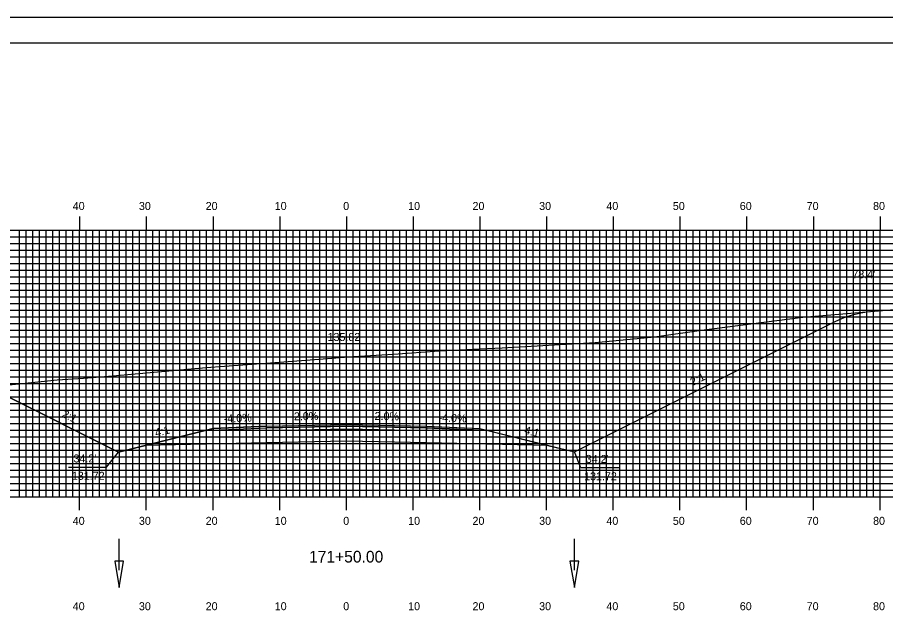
# Model space of a CAD drawing. Extents: x 1782647 to 1782990, y 442591 to 442811.
# Drawn here: x 1782763.6 to 1782893.8, y 442721.2 to 442810.5 of the extents above; entities that cross this region are included whole.
import ezdxf

# ---------------------------------------------------------------- set-up
doc = ezdxf.new("R2010")
doc.units = 0
for name, color, linetype in [('ANNOTATION', 7, 'Continuous'), ('BORDER', 7, 'Continuous'), ('D_Drainage_Ditch_Line', 7, 'Continuous'), ('D_Roadway_Centerline', 7, 'Continuous'), ('D_Roadway_Centerline_Text', 7, 'Continuous'), ('D_Roadway_Edge_Shoulder', 7, 'Continuous'), ('D_Roadway_Edge_TW', 7, 'Continuous'), ('D_Roadway_Pavement', 7, 'Continuous'), ('D_Roadway_SlopeLines', 7, 'Continuous'), ('D_Roadway_SubGrade', 7, 'Continuous'), ('D_Text_Standard', 7, 'Continuous'), ('H_V ANNOTATION', 7, 'Continuous'), ('MAJOR', 7, 'Continuous'), ('MINOR', 7, 'Continuous'), ('PLOT BOUNDARY', 7, 'Continuous'), ('S_Roadway_Centerline', 7, 'Continuous')]:
    doc.layers.add(name, color=color, linetype=linetype)

msp = doc.modelspace()

# ---------------------------------------------------------------- linework, layer by layer
at = {"layer": 'ANNOTATION'}
for points in [[(1782771.3, 442743.1), (1782776.99, 442743.1), (1782778.77, 442745.38)], [(1782853.78, 442743.03), (1782848.09, 442743.03), (1782847.12, 442745.39)]]:
    msp.add_lwpolyline(points, dxfattribs=at)
at = {"layer": 'BORDER'}
msp.add_lwpolyline([(1782663.35, 442596.67), (1782983.35, 442596.67), (1782983.35, 442806.67), (1782663.35, 442806.67)], close=True, dxfattribs=at)
at = {"layer": 'D_Drainage_Ditch_Line'}
for p, q in [((1782778.87, 442727.69), (1782778.87, 442732.39)), ((1782847.12, 442727.69), (1782847.12, 442732.39))]:
    msp.add_line(p, q, dxfattribs=at)
for points in [[(1782779.53, 442729), (1782778.21, 442729), (1782778.87, 442725.07)], [(1782847.77, 442729), (1782846.46, 442729), (1782847.12, 442725.07)]]:
    msp.add_lwpolyline(points, close=True, dxfattribs=at)
at = {"layer": 'D_Roadway_Centerline'}
msp.add_lwpolyline([(1782756.76, 442754.88), (1782758.01, 442754.92), (1782759.26, 442754.76), (1782760.51, 442754.42), (1782761.76, 442753.89), (1782778.77, 442745.38), (1782782.77, 442746.38), (1782792.95, 442748.93), (1782800.95, 442749.25), (1782812.95, 442749.49), (1782824.95, 442749.25), (1782832.95, 442748.93), (1782843.12, 442746.38), (1782847.12, 442745.39), (1782886.31, 442764.98), (1782887.56, 442765.54), (1782888.81, 442765.97), (1782890.06, 442766.27), (1782891.31, 442766.44)], dxfattribs=at)
at = {"layer": 'D_Roadway_Edge_Shoulder'}
for points in [[(1782800.95, 442749.25), (1782792.95, 442748.93), (1782792.95, 442748.68), (1782800.95, 442749)], [(1782824.95, 442749.25), (1782832.95, 442748.93), (1782832.95, 442748.68), (1782824.95, 442749)]]:
    msp.add_lwpolyline(points, close=True, dxfattribs=at)
at = {"layer": 'D_Roadway_Edge_TW'}
msp.add_lwpolyline([(1782800.95, 442749), (1782800.95, 442749.25), (1782812.95, 442749.49), (1782824.95, 442749.25), (1782824.95, 442749), (1782812.95, 442749.24)], close=True, dxfattribs=at)
at = {"layer": 'D_Roadway_Pavement'}
msp.add_lwpolyline([(1782800.95, 442748.58), (1782800.95, 442749), (1782812.95, 442749.24), (1782824.95, 442749), (1782824.95, 442748.58), (1782812.95, 442748.82)], close=True, dxfattribs=at)
at = {"layer": 'D_Roadway_SlopeLines'}
for points in [[(1782847.12, 442745.39), (1782886.31, 442764.98), (1782887.56, 442765.54), (1782888.81, 442765.97), (1782890.06, 442766.27), (1782891.31, 442766.44)], [(1782778.77, 442745.38), (1782761.76, 442753.89), (1782760.51, 442754.42), (1782759.26, 442754.76), (1782758.01, 442754.92), (1782756.76, 442754.88)], [(1782792.95, 442748.93), (1782778.77, 442745.38)], [(1782832.95, 442748.93), (1782847.12, 442745.39)]]:
    msp.add_lwpolyline(points, dxfattribs=at)
at = {"layer": 'D_Roadway_SubGrade'}
msp.add_lwpolyline([(1782800.95, 442746.75), (1782782.77, 442746.38), (1782792.95, 442748.93), (1782792.95, 442748.68), (1782800.95, 442749), (1782812.95, 442749.24), (1782824.95, 442749), (1782832.95, 442748.68), (1782832.95, 442748.93), (1782843.12, 442746.38), (1782824.95, 442746.75), (1782812.95, 442746.99)], close=True, dxfattribs=at)
at = {"layer": 'MAJOR'}
for p, q in [((1782772.95, 442780.67), (1782772.95, 442778.67)), ((1782782.95, 442780.67), (1782782.95, 442778.67)), ((1782792.95, 442780.67), (1782792.95, 442778.67)), ((1782802.95, 442780.67), (1782802.95, 442778.67)), ((1782812.95, 442780.67), (1782812.95, 442778.67)), ((1782822.95, 442780.67), (1782822.95, 442778.67)), ((1782832.95, 442780.67), (1782832.95, 442778.67)), ((1782842.95, 442780.67), (1782842.95, 442778.67)), ((1782852.95, 442780.67), (1782852.95, 442778.67)), ((1782862.95, 442780.67), (1782862.95, 442778.67)), ((1782872.95, 442780.67), (1782872.95, 442778.67)), ((1782882.95, 442780.67), (1782882.95, 442778.67)), ((1782892.95, 442780.67), (1782892.95, 442778.67)), ((1782672.95, 442778.67), (1782952.95, 442778.67)), ((1782672.95, 442778.67), (1782952.95, 442778.67)), ((1782772.95, 442738.67), (1782772.95, 442778.67)), ((1782782.95, 442738.67), (1782782.95, 442778.67)), ((1782792.95, 442738.67), (1782792.95, 442778.67)), ((1782802.95, 442738.67), (1782802.95, 442778.67)), ((1782812.95, 442738.67), (1782812.95, 442778.67)), ((1782822.95, 442738.67), (1782822.95, 442778.67)), ((1782832.95, 442738.67), (1782832.95, 442778.67)), ((1782842.95, 442738.67), (1782842.95, 442778.67)), ((1782852.95, 442738.67), (1782852.95, 442778.67)), ((1782862.95, 442738.67), (1782862.95, 442778.67)), ((1782872.95, 442738.67), (1782872.95, 442778.67)), ((1782882.95, 442738.67), (1782882.95, 442778.67)), ((1782892.95, 442738.67), (1782892.95, 442778.67)), ((1782672.95, 442773.67), (1782952.95, 442773.67)), ((1782672.95, 442768.67), (1782952.95, 442768.67)), ((1782672.95, 442763.67), (1782952.95, 442763.67)), ((1782672.95, 442758.67), (1782952.95, 442758.67)), ((1782672.95, 442753.67), (1782952.95, 442753.67)), ((1782672.95, 442748.67), (1782952.95, 442748.67)), ((1782672.95, 442743.67), (1782952.95, 442743.67)), ((1782672.95, 442738.67), (1782952.95, 442738.67)), ((1782672.95, 442738.67), (1782952.95, 442738.67)), ((1782772.95, 442736.66), (1782772.95, 442738.67)), ((1782782.95, 442736.66), (1782782.95, 442738.67)), ((1782792.95, 442736.66), (1782792.95, 442738.67)), ((1782802.95, 442736.66), (1782802.95, 442738.67)), ((1782812.95, 442736.66), (1782812.95, 442738.67)), ((1782822.95, 442736.66), (1782822.95, 442738.67)), ((1782832.95, 442736.66), (1782832.95, 442738.67)), ((1782842.95, 442736.66), (1782842.95, 442738.67)), ((1782852.95, 442736.66), (1782852.95, 442738.67)), ((1782862.95, 442736.66), (1782862.95, 442738.67)), ((1782872.95, 442736.66), (1782872.95, 442738.67)), ((1782882.95, 442736.66), (1782882.95, 442738.67)), ((1782892.95, 442736.66), (1782892.95, 442738.67))]:
    msp.add_line(p, q, dxfattribs=at)
at = {"layer": 'MINOR'}
for p, q in [((1782672.95, 442777.67), (1782952.95, 442777.67)), ((1782763.95, 442738.67), (1782763.95, 442778.67)), ((1782764.95, 442738.67), (1782764.95, 442778.67)), ((1782765.95, 442738.67), (1782765.95, 442778.67)), ((1782766.95, 442738.67), (1782766.95, 442778.67)), ((1782767.95, 442738.67), (1782767.95, 442778.67)), ((1782768.95, 442738.67), (1782768.95, 442778.67)), ((1782769.95, 442738.67), (1782769.95, 442778.67)), ((1782770.95, 442738.67), (1782770.95, 442778.67)), ((1782771.95, 442738.67), (1782771.95, 442778.67)), ((1782773.95, 442738.67), (1782773.95, 442778.67)), ((1782774.95, 442738.67), (1782774.95, 442778.67)), ((1782775.95, 442738.67), (1782775.95, 442778.67)), ((1782776.95, 442738.67), (1782776.95, 442778.67)), ((1782777.95, 442738.67), (1782777.95, 442778.67)), ((1782778.95, 442738.67), (1782778.95, 442778.67)), ((1782779.95, 442738.67), (1782779.95, 442778.67)), ((1782780.95, 442738.67), (1782780.95, 442778.67)), ((1782781.95, 442738.67), (1782781.95, 442778.67)), ((1782783.95, 442738.67), (1782783.95, 442778.67)), ((1782784.95, 442738.67), (1782784.95, 442778.67)), ((1782785.95, 442738.67), (1782785.95, 442778.67)), ((1782786.95, 442738.67), (1782786.95, 442778.67)), ((1782787.95, 442738.67), (1782787.95, 442778.67)), ((1782788.95, 442738.67), (1782788.95, 442778.67)), ((1782789.95, 442738.67), (1782789.95, 442778.67)), ((1782790.95, 442738.67), (1782790.95, 442778.67)), ((1782791.95, 442738.67), (1782791.95, 442778.67)), ((1782793.95, 442738.67), (1782793.95, 442778.67)), ((1782794.95, 442738.67), (1782794.95, 442778.67)), ((1782795.95, 442738.67), (1782795.95, 442778.67)), ((1782796.95, 442738.67), (1782796.95, 442778.67)), ((1782797.95, 442738.67), (1782797.95, 442778.67)), ((1782798.95, 442738.67), (1782798.95, 442778.67)), ((1782799.95, 442738.67), (1782799.95, 442778.67)), ((1782800.95, 442738.67), (1782800.95, 442778.67)), ((1782801.95, 442738.67), (1782801.95, 442778.67)), ((1782803.95, 442738.67), (1782803.95, 442778.67)), ((1782804.95, 442738.67), (1782804.95, 442778.67)), ((1782805.95, 442738.67), (1782805.95, 442778.67)), ((1782806.95, 442738.67), (1782806.95, 442778.67)), ((1782807.95, 442738.67), (1782807.95, 442778.67)), ((1782808.95, 442738.67), (1782808.95, 442778.67)), ((1782809.95, 442738.67), (1782809.95, 442778.67)), ((1782810.95, 442738.67), (1782810.95, 442778.67)), ((1782811.95, 442738.67), (1782811.95, 442778.67)), ((1782813.95, 442738.67), (1782813.95, 442778.67)), ((1782814.95, 442738.67), (1782814.95, 442778.67)), ((1782815.95, 442738.67), (1782815.95, 442778.67)), ((1782816.95, 442738.67), (1782816.95, 442778.67)), ((1782817.95, 442738.67), (1782817.95, 442778.67)), ((1782818.95, 442738.67), (1782818.95, 442778.67)), ((1782819.95, 442738.67), (1782819.95, 442778.67)), ((1782820.95, 442738.67), (1782820.95, 442778.67)), ((1782821.95, 442738.67), (1782821.95, 442778.67)), ((1782823.95, 442738.67), (1782823.95, 442778.67)), ((1782824.95, 442738.67), (1782824.95, 442778.67)), ((1782825.95, 442738.67), (1782825.95, 442778.67)), ((1782826.95, 442738.67), (1782826.95, 442778.67)), ((1782827.95, 442738.67), (1782827.95, 442778.67)), ((1782828.95, 442738.67), (1782828.95, 442778.67)), ((1782829.95, 442738.67), (1782829.95, 442778.67)), ((1782830.95, 442738.67), (1782830.95, 442778.67)), ((1782831.95, 442738.67), (1782831.95, 442778.67)), ((1782833.95, 442738.67), (1782833.95, 442778.67)), ((1782834.95, 442738.67), (1782834.95, 442778.67)), ((1782835.95, 442738.67), (1782835.95, 442778.67)), ((1782836.95, 442738.67), (1782836.95, 442778.67)), ((1782837.95, 442738.67), (1782837.95, 442778.67)), ((1782838.95, 442738.67), (1782838.95, 442778.67)), ((1782839.95, 442738.67), (1782839.95, 442778.67)), ((1782840.95, 442738.67), (1782840.95, 442778.67)), ((1782841.95, 442738.67), (1782841.95, 442778.67)), ((1782843.95, 442738.67), (1782843.95, 442778.67)), ((1782844.95, 442738.67), (1782844.95, 442778.67)), ((1782845.95, 442738.67), (1782845.95, 442778.67)), ((1782846.95, 442738.67), (1782846.95, 442778.67)), ((1782847.95, 442738.67), (1782847.95, 442778.67)), ((1782848.95, 442738.67), (1782848.95, 442778.67)), ((1782849.95, 442738.67), (1782849.95, 442778.67)), ((1782850.95, 442738.67), (1782850.95, 442778.67)), ((1782851.95, 442738.67), (1782851.95, 442778.67)), ((1782853.95, 442738.67), (1782853.95, 442778.67)), ((1782854.95, 442738.67), (1782854.95, 442778.67)), ((1782855.95, 442738.67), (1782855.95, 442778.67)), ((1782856.95, 442738.67), (1782856.95, 442778.67)), ((1782857.95, 442738.67), (1782857.95, 442778.67)), ((1782858.95, 442738.67), (1782858.95, 442778.67)), ((1782859.95, 442738.67), (1782859.95, 442778.67)), ((1782860.95, 442738.67), (1782860.95, 442778.67)), ((1782861.95, 442738.67), (1782861.95, 442778.67)), ((1782863.95, 442738.67), (1782863.95, 442778.67)), ((1782864.95, 442738.67), (1782864.95, 442778.67)), ((1782865.95, 442738.67), (1782865.95, 442778.67)), ((1782866.95, 442738.67), (1782866.95, 442778.67)), ((1782867.95, 442738.67), (1782867.95, 442778.67)), ((1782868.95, 442738.67), (1782868.95, 442778.67)), ((1782869.95, 442738.67), (1782869.95, 442778.67)), ((1782870.95, 442738.67), (1782870.95, 442778.67)), ((1782871.95, 442738.67), (1782871.95, 442778.67)), ((1782873.95, 442738.67), (1782873.95, 442778.67)), ((1782874.95, 442738.67), (1782874.95, 442778.67)), ((1782875.95, 442738.67), (1782875.95, 442778.67)), ((1782876.95, 442738.67), (1782876.95, 442778.67)), ((1782877.95, 442738.67), (1782877.95, 442778.67)), ((1782878.95, 442738.67), (1782878.95, 442778.67)), ((1782879.95, 442738.67), (1782879.95, 442778.67)), ((1782880.95, 442738.67), (1782880.95, 442778.67)), ((1782881.95, 442738.67), (1782881.95, 442778.67)), ((1782883.95, 442738.67), (1782883.95, 442778.67)), ((1782884.95, 442738.67), (1782884.95, 442778.67)), ((1782885.95, 442738.67), (1782885.95, 442778.67)), ((1782886.95, 442738.67), (1782886.95, 442778.67)), ((1782887.95, 442738.67), (1782887.95, 442778.67)), ((1782888.95, 442738.67), (1782888.95, 442778.67)), ((1782889.95, 442738.67), (1782889.95, 442778.67)), ((1782890.95, 442738.67), (1782890.95, 442778.67)), ((1782891.95, 442738.67), (1782891.95, 442778.67)), ((1782672.95, 442776.67), (1782952.95, 442776.67)), ((1782672.95, 442775.67), (1782952.95, 442775.67)), ((1782672.95, 442774.67), (1782952.95, 442774.67)), ((1782672.95, 442772.67), (1782952.95, 442772.67)), ((1782672.95, 442771.67), (1782952.95, 442771.67)), ((1782672.95, 442770.67), (1782952.95, 442770.67)), ((1782672.95, 442769.67), (1782952.95, 442769.67)), ((1782672.95, 442767.67), (1782952.95, 442767.67)), ((1782672.95, 442766.67), (1782952.95, 442766.67)), ((1782672.95, 442765.67), (1782952.95, 442765.67)), ((1782672.95, 442764.67), (1782952.95, 442764.67)), ((1782672.95, 442762.67), (1782952.95, 442762.67)), ((1782672.95, 442761.67), (1782952.95, 442761.67)), ((1782672.95, 442760.67), (1782952.95, 442760.67)), ((1782672.95, 442759.67), (1782952.95, 442759.67)), ((1782672.95, 442757.67), (1782952.95, 442757.67)), ((1782672.95, 442756.67), (1782952.95, 442756.67)), ((1782672.95, 442755.67), (1782952.95, 442755.67)), ((1782672.95, 442754.67), (1782952.95, 442754.67)), ((1782672.95, 442752.67), (1782952.95, 442752.67)), ((1782672.95, 442751.67), (1782952.95, 442751.67)), ((1782672.95, 442750.67), (1782952.95, 442750.67)), ((1782672.95, 442749.67), (1782952.95, 442749.67)), ((1782672.95, 442747.67), (1782952.95, 442747.67)), ((1782672.95, 442746.67), (1782952.95, 442746.67)), ((1782672.95, 442745.67), (1782952.95, 442745.67)), ((1782672.95, 442744.67), (1782952.95, 442744.67)), ((1782672.95, 442742.67), (1782952.95, 442742.67)), ((1782672.95, 442741.67), (1782952.95, 442741.67)), ((1782672.95, 442740.67), (1782952.95, 442740.67)), ((1782672.95, 442739.67), (1782952.95, 442739.67))]:
    msp.add_line(p, q, dxfattribs=at)
at = {"layer": 'PLOT BOUNDARY'}
msp.add_lwpolyline([(1782647.16, 442590.55), (1782987.16, 442590.55), (1782987.16, 442810.55), (1782647.16, 442810.55)], close=True, dxfattribs=at)
at = {"layer": 'S_Roadway_Centerline'}
msp.add_lwpolyline([(1782754.65, 442754.66), (1782769.59, 442756.23), (1782773.53, 442756.47), (1782777.92, 442756.82), (1782791.93, 442758.04), (1782802.94, 442758.84), (1782808.83, 442759.31), (1782813.97, 442759.69), (1782819.99, 442760.06), (1782826.85, 442760.54), (1782831.87, 442760.79), (1782836.3, 442761.01), (1782850.24, 442761.82), (1782859.12, 442762.66), (1782866.16, 442763.64), (1782881.37, 442765.6), (1782898.09, 442767.02), (1782905.02, 442767.66), (1782922.69, 442768.98), (1782924.84, 442769.07), (1782927.08, 442769.26), (1782945.37, 442770.51), (1782950.53, 442770.74), (1782952.95, 442770.91)], dxfattribs=at)

# ---------------------------------------------------------------- texts
at = {"layer": 'ANNOTATION'}
for s, rotation, p in [('2:1', 26.5651, (1782864.86, 442755.29)), ('2:1', 333.4349, (1782770.2, 442750.71)), ('-4.0%', 2.2906, (1782794.58, 442749.79)), ('-2.0%', 1.1458, (1782804.55, 442750.12)), ('-2.0%', 358.8542, (1782816.63, 442750.21)), ('-4.0%', 357.7094, (1782826.74, 442749.98)), ('4:1', 14.0362, (1782784.4, 442747.65)), ('4:1', 345.9638, (1782839.54, 442748.14))]:
    msp.add_text(s, height=1.2, rotation=rotation, dxfattribs=at).set_placement(p)
for s, p in [("34.2'", (1782772.03, 442743.82)), ("34.2'", (1782848.83, 442743.75)), ('131.72', (1782771.79, 442741.22)), ('131.72', (1782848.58, 442741.15))]:
    msp.add_text(s, height=1.2, dxfattribs=at).set_placement(p)
at = {"layer": 'D_Roadway_Centerline'}
for s, p in [('C', (1782812.94, 442749.49)), ('L', (1782812.95, 442749.48))]:
    msp.add_text(s, height=0.0146, dxfattribs=at).set_placement(p)
at = {"layer": 'D_Roadway_Centerline_Text'}
msp.add_text('135.82', height=1.2, dxfattribs=at).set_placement((1782810.12, 442762.03))
at = {"layer": 'D_Text_Standard'}
msp.add_text("78.4'", height=1.2, dxfattribs=at).set_placement((1782888.79, 442771.43))
at = {"layer": 'H_V ANNOTATION'}
for s, height, p in [('40', 1.2, (1782771.92, 442781.67)), ('30', 1.2, (1782781.84, 442781.67)), ('20', 1.2, (1782791.85, 442781.67)), ('10', 1.2, (1782802.2, 442781.67)), ('0', 1.2, (1782812.47, 442781.67)), ('10', 1.2, (1782822.2, 442781.67)), ('20', 1.2, (1782831.85, 442781.67)), ('30', 1.2, (1782841.84, 442781.67)), ('40', 1.2, (1782851.92, 442781.67)), ('50', 1.2, (1782861.88, 442781.67)), ('60', 1.2, (1782871.92, 442781.67)), ('70', 1.2, (1782881.95, 442781.67)), ('80', 1.2, (1782891.9, 442781.67)), ('40', 1.2, (1782771.92, 442734.47)), ('30', 1.2, (1782781.84, 442734.47)), ('20', 1.2, (1782791.85, 442734.47)), ('10', 1.2, (1782802.2, 442734.47)), ('0', 1.2, (1782812.47, 442734.47)), ('10', 1.2, (1782822.2, 442734.47)), ('20', 1.2, (1782831.85, 442734.47)), ('30', 1.2, (1782841.84, 442734.47)), ('40', 1.2, (1782851.92, 442734.47)), ('50', 1.2, (1782861.88, 442734.47)), ('60', 1.2, (1782871.92, 442734.47)), ('70', 1.2, (1782881.95, 442734.47)), ('80', 1.2, (1782891.9, 442734.47)), ('171+50.00', 1.75, (1782807.34, 442728.82)), ('40', 1.2, (1782771.92, 442721.67)), ('30', 1.2, (1782781.84, 442721.67)), ('20', 1.2, (1782791.85, 442721.67)), ('10', 1.2, (1782802.2, 442721.67)), ('0', 1.2, (1782812.47, 442721.67)), ('10', 1.2, (1782822.2, 442721.67)), ('20', 1.2, (1782831.85, 442721.67)), ('30', 1.2, (1782841.84, 442721.67)), ('40', 1.2, (1782851.92, 442721.67)), ('50', 1.2, (1782861.88, 442721.67)), ('60', 1.2, (1782871.92, 442721.67)), ('70', 1.2, (1782881.95, 442721.67)), ('80', 1.2, (1782891.9, 442721.67))]:
    msp.add_text(s, height=height, dxfattribs=at).set_placement(p)

doc.saveas('drawing.dxf')
